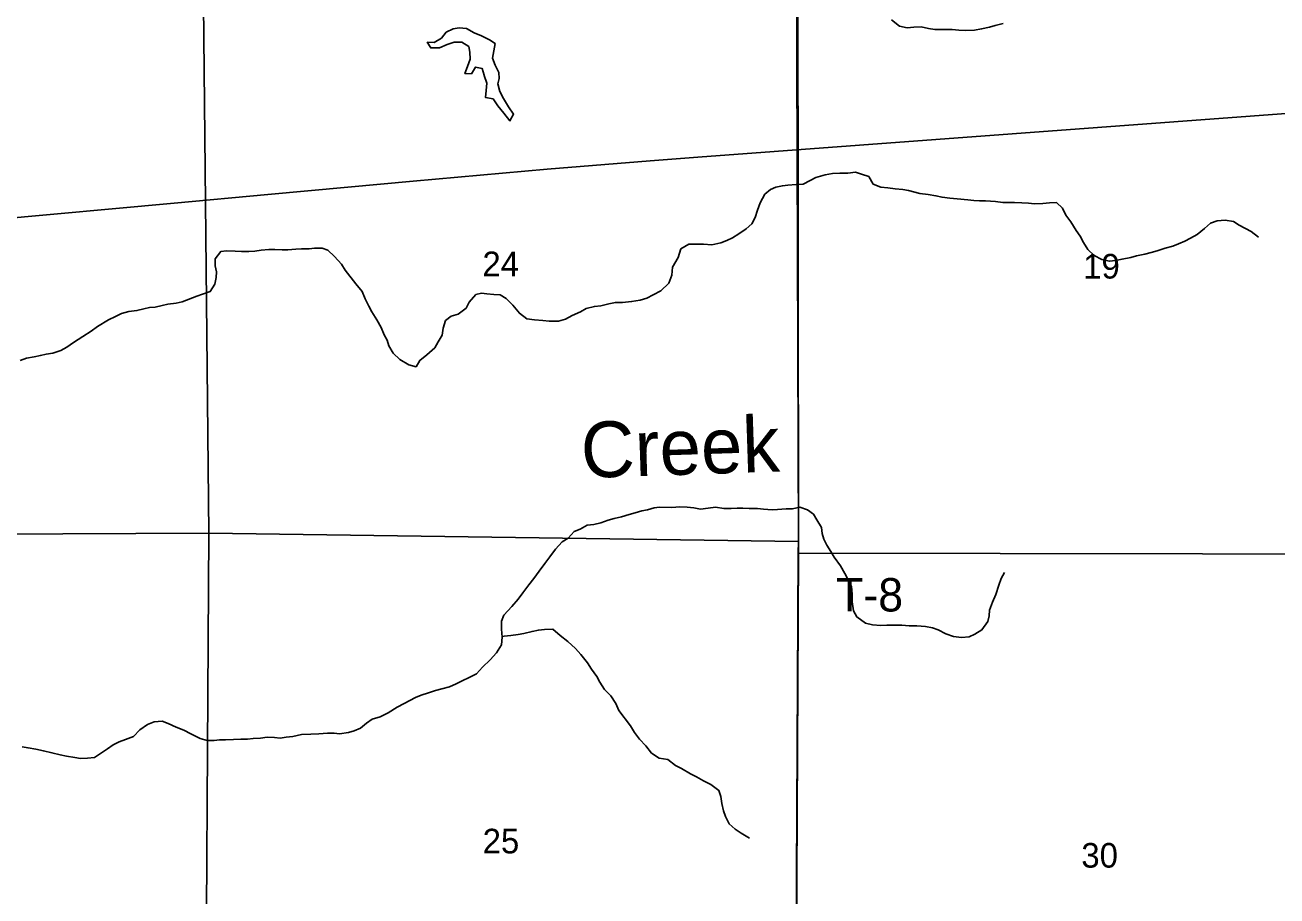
# Model space of a CAD drawing. Extents: x 1772825 to 1773716, y 1138558 to 1139032.
# Drawn here: x 1772830.361 to 1772831.426, y 1138561.834 to 1138562.575 of the extents above; entities that cross this region are included whole.
import ezdxf

# ---------------------------------------------------------------- set-up
doc = ezdxf.new("R2010")
doc.units = 0
for name, color, linetype in [('GM_X_Minor_Lake', 7, 'Continuous'), ('GM_X_Minor_River', 7, 'Continuous'), ('GM_X_Minor_River_Text', 7, 'Continuous'), ('GM_X_Rail_Line', 7, 'Continuous'), ('GM_X_Section', 7, 'Continuous'), ('GM_X_Section_Text', 7, 'Continuous'), ('GM_X_Township', 7, 'Continuous'), ('GM_X_Township_Road_Text', 7, 'Continuous')]:
    doc.layers.add(name, color=color, linetype=linetype)

msp = doc.modelspace()

# ---------------------------------------------------------------- linework, layer by layer
at = {"layer": 'GM_X_Minor_Lake'}
for points in [[(1772830.7608, 1138562.5591), (1772830.7559, 1138562.5621), (1772830.7493, 1138562.5656), (1772830.743, 1138562.5682), (1772830.7364, 1138562.5717), (1772830.7301, 1138562.5723), (1772830.7252, 1138562.5714), (1772830.7193, 1138562.5687), (1772830.7153, 1138562.5636), (1772830.709, 1138562.56), (1772830.7031, 1138562.5601), (1772830.7061, 1138562.5553), (1772830.7135, 1138562.5555), (1772830.72, 1138562.5583), (1772830.7261, 1138562.5603), (1772830.7325, 1138562.5603), (1772830.7384, 1138562.5565), (1772830.7393, 1138562.5518), (1772830.7397, 1138562.5457), (1772830.7372, 1138562.5396), (1772830.7351, 1138562.5335), (1772830.7406, 1138562.5333), (1772830.744, 1138562.539), (1772830.7497, 1138562.5379), (1772830.7515, 1138562.5322)], [(1772830.7515, 1138562.5322), (1772830.7516, 1138562.5318), (1772830.7538, 1138562.5253), (1772830.7531, 1138562.5192), (1772830.7526, 1138562.5132), (1772830.7591, 1138562.512), (1772830.7631, 1138562.5061), (1772830.7683, 1138562.4998), (1772830.7734, 1138562.4933), (1772830.7765, 1138562.499), (1772830.7722, 1138562.5053), (1772830.768, 1138562.5122), (1772830.7648, 1138562.5182), (1772830.7631, 1138562.5247), (1772830.7643, 1138562.5294), (1772830.7639, 1138562.5344), (1772830.7609, 1138562.5407), (1772830.7587, 1138562.5467), (1772830.7608, 1138562.5591)]]:
    msp.add_lwpolyline(points, dxfattribs=at)
at = {"layer": 'GM_X_Minor_River'}
for points in [[(1772831.098, 1138562.5791), (1772831.1048, 1138562.5737), (1772831.1114, 1138562.5724), (1772831.1169, 1138562.5729), (1772831.1232, 1138562.5731), (1772831.1295, 1138562.5719), (1772831.1348, 1138562.571), (1772831.1496, 1138562.5709), (1772831.1551, 1138562.5703), (1772831.1613, 1138562.5701), (1772831.1684, 1138562.5704), (1772831.1746, 1138562.5714), (1772831.1813, 1138562.5729), (1772831.1862, 1138562.5743), (1772831.1929, 1138562.5762)], [(1772830.7879, 1138562.3249), (1772830.7944, 1138562.3242), (1772830.8014, 1138562.3234), (1772830.8069, 1138562.323), (1772830.8147, 1138562.3229), (1772830.8208, 1138562.3248), (1772830.8263, 1138562.3278), (1772830.8335, 1138562.331), (1772830.8383, 1138562.3338), (1772830.8453, 1138562.3355), (1772830.8506, 1138562.3359), (1772830.8574, 1138562.3377), (1772830.8631, 1138562.3389), (1772830.8692, 1138562.3388), (1772830.8768, 1138562.3396), (1772830.8842, 1138562.3409), (1772830.8897, 1138562.3424), (1772830.8951, 1138562.3454), (1772830.9017, 1138562.3488), (1772830.9086, 1138562.3554), (1772830.9111, 1138562.362), (1772830.9117, 1138562.3688), (1772830.9164, 1138562.3772), (1772830.9189, 1138562.3844), (1772830.9256, 1138562.3883), (1772830.9321, 1138562.3885), (1772830.9381, 1138562.3883), (1772830.9451, 1138562.3879), (1772830.9529, 1138562.3897), (1772830.9579, 1138562.3916), (1772830.9626, 1138562.3939), (1772830.9682, 1138562.3971), (1772830.9744, 1138562.4016), (1772830.9792, 1138562.4057), (1772830.9821, 1138562.411), (1772830.984, 1138562.4173), (1772830.9863, 1138562.4237), (1772830.9901, 1138562.4309), (1772830.9949, 1138562.4349), (1772830.9996, 1138562.437), (1772831.0051, 1138562.4381), (1772831.0099, 1138562.4386), (1772831.0169, 1138562.4392), (1772831.0228, 1138562.4395), (1772831.0287, 1138562.4427), (1772831.0336, 1138562.4452), (1772831.0414, 1138562.4474), (1772831.0479, 1138562.4485), (1772831.054, 1138562.4487), (1772831.0608, 1138562.4489), (1772831.0674, 1138562.4496), (1772831.0724, 1138562.4479), (1772831.0786, 1138562.4461), (1772831.0824, 1138562.4395), (1772831.089, 1138562.437), (1772831.0947, 1138562.4362), (1772831.1012, 1138562.4354), (1772831.1076, 1138562.4348), (1772831.1124, 1138562.434), (1772831.122, 1138562.4315), (1772831.1291, 1138562.4307), (1772831.1357, 1138562.4296), (1772831.141, 1138562.4284), (1772831.1476, 1138562.4276), (1772831.1539, 1138562.427), (1772831.1628, 1138562.4262), (1772831.1679, 1138562.4256), (1772831.1729, 1138562.4252), (1772831.178, 1138562.4252), (1772831.1863, 1138562.4246), (1772831.1926, 1138562.424), (1772831.1974, 1138562.424), (1772831.2027, 1138562.4238), (1772831.2087, 1138562.4236), (1772831.2146, 1138562.4232), (1772831.2196, 1138562.4228), (1772831.2266, 1138562.4229), (1772831.2323, 1138562.4235), (1772831.2384, 1138562.4238), (1772831.2433, 1138562.4191), (1772831.2463, 1138562.413), (1772831.2504, 1138562.4074), (1772831.2551, 1138562.4), (1772831.2585, 1138562.3951), (1772831.2612, 1138562.3899), (1772831.2648, 1138562.384), (1772831.2704, 1138562.3789), (1772831.2769, 1138562.3755), (1772831.2833, 1138562.3739), (1772831.2886, 1138562.3745), (1772831.2941, 1138562.3758), (1772831.3014, 1138562.3772), (1772831.3063, 1138562.3784), (1772831.3133, 1138562.38), (1772831.3188, 1138562.3813), (1772831.3238, 1138562.3828), (1772831.3308, 1138562.3849), (1772831.3373, 1138562.3868), (1772831.342, 1138562.3887), (1772831.3473, 1138562.3909), (1772831.3523, 1138562.3934)], [(1772831.3523, 1138562.3934), (1772831.3578, 1138562.3966), (1772831.3643, 1138562.4018), (1772831.3692, 1138562.4062), (1772831.3749, 1138562.4083), (1772831.3818, 1138562.4088), (1772831.3888, 1138562.4076), (1772831.3937, 1138562.4046), (1772831.4039, 1138562.3992), (1772831.4102, 1138562.3944)], [(1772830.3569, 1138562.2894), (1772830.3623, 1138562.2914), (1772830.3687, 1138562.2927), (1772830.374, 1138562.2939), (1772830.379, 1138562.295), (1772830.3845, 1138562.2957), (1772830.3913, 1138562.298), (1772830.3965, 1138562.3008), (1772830.4022, 1138562.3047), (1772830.4102, 1138562.3098), (1772830.4172, 1138562.3144), (1772830.4225, 1138562.3183), (1772830.432, 1138562.324), (1772830.4378, 1138562.327), (1772830.4431, 1138562.3296), (1772830.4494, 1138562.3311), (1772830.4562, 1138562.332), (1772830.4621, 1138562.3335), (1772830.4668, 1138562.3345), (1772830.4716, 1138562.3348), (1772830.4777, 1138562.3363), (1772830.4824, 1138562.3374), (1772830.4894, 1138562.3383), (1772830.4946, 1138562.3395), (1772830.5071, 1138562.3443), (1772830.512, 1138562.3458), (1772830.5185, 1138562.3483), (1772830.5223, 1138562.3543), (1772830.5235, 1138562.3602), (1772830.5237, 1138562.365), (1772830.5228, 1138562.3699), (1772830.5228, 1138562.376), (1772830.5274, 1138562.3822), (1772830.5323, 1138562.3828), (1772830.5397, 1138562.3824), (1772830.545, 1138562.3821), (1772830.5513, 1138562.3821), (1772830.5564, 1138562.3825), (1772830.5617, 1138562.3832), (1772830.5684, 1138562.3839), (1772830.5733, 1138562.3839), (1772830.5798, 1138562.3837), (1772830.5845, 1138562.3837), (1772830.5912, 1138562.3842), (1772830.5961, 1138562.3844), (1772830.6026, 1138562.3846), (1772830.6073, 1138562.3851), (1772830.6138, 1138562.3849), (1772830.6185, 1138562.3832), (1772830.6243, 1138562.378), (1772830.6302, 1138562.3713), (1772830.6332, 1138562.3662), (1772830.6423, 1138562.3548), (1772830.6478, 1138562.3483), (1772830.6504, 1138562.342), (1772830.6534, 1138562.3358), (1772830.656, 1138562.3308), (1772830.6602, 1138562.324), (1772830.6638, 1138562.3177), (1772830.6664, 1138562.3114), (1772830.669, 1138562.3067), (1772830.6705, 1138562.3019), (1772830.6741, 1138562.2958), (1772830.6798, 1138562.2903), (1772830.6874, 1138562.2857), (1772830.6936, 1138562.2842), (1772830.6967, 1138562.2896), (1772830.7026, 1138562.2944), (1772830.7096, 1138562.3004), (1772830.7123, 1138562.3055), (1772830.7159, 1138562.311), (1772830.7167, 1138562.3171), (1772830.7186, 1138562.3235), (1772830.7234, 1138562.3271), (1772830.7295, 1138562.329), (1772830.7361, 1138562.3339), (1772830.7388, 1138562.3392), (1772830.7444, 1138562.3456), (1772830.7491, 1138562.3467), (1772830.7538, 1138562.3462), (1772830.7597, 1138562.3457), (1772830.7652, 1138562.3453), (1772830.7702, 1138562.3421), (1772830.776, 1138562.3366), (1772830.7815, 1138562.3297), (1772830.7879, 1138562.3249)], [(1772830.7329, 1138562.017), (1772830.7388, 1138562.02), (1772830.7451, 1138562.023), (1772830.75, 1138562.0288), (1772830.7567, 1138562.0349), (1772830.7619, 1138562.0409), (1772830.7661, 1138562.0478), (1772830.7669, 1138562.0542), (1772830.7663, 1138562.061), (1772830.7663, 1138562.0679), (1772830.7681, 1138562.073), (1772830.7751, 1138562.0804), (1772830.7803, 1138562.0866), (1772830.7845, 1138562.0921), (1772830.7894, 1138562.0989), (1772830.7938, 1138562.1042), (1772830.7982, 1138562.1104), (1772830.803, 1138562.1169), (1772830.8074, 1138562.1225), (1772830.8122, 1138562.1292), (1772830.8179, 1138562.1352), (1772830.823, 1138562.1384), (1772830.828, 1138562.1441), (1772830.8331, 1138562.1462), (1772830.8392, 1138562.1494), (1772830.8447, 1138562.1501), (1772830.8508, 1138562.1514), (1772830.857, 1138562.1538), (1772830.862, 1138562.1553), (1772830.8683, 1138562.1565), (1772830.8747, 1138562.1587), (1772830.88, 1138562.16), (1772830.8856, 1138562.1617), (1772830.8903, 1138562.1626), (1772830.896, 1138562.1641), (1772830.9007, 1138562.1647), (1772830.911, 1138562.1646), (1772830.9178, 1138562.1652), (1772830.9241, 1138562.1649), (1772830.9298, 1138562.1642), (1772830.9355, 1138562.1632), (1772830.9419, 1138562.1639), (1772830.9482, 1138562.1648), (1772830.9554, 1138562.1637), (1772830.9615, 1138562.1638), (1772830.9666, 1138562.164), (1772830.9715, 1138562.164), (1772830.9769, 1138562.1636), (1772830.9839, 1138562.1637), (1772830.9892, 1138562.1632), (1772830.9964, 1138562.1626), (1772831.0011, 1138562.1627), (1772831.0084, 1138562.1635), (1772831.0137, 1138562.1634), (1772831.0199, 1138562.1647), (1772831.0266, 1138562.1626), (1772831.0315, 1138562.1588), (1772831.0345, 1138562.1539), (1772831.0383, 1138562.1474), (1772831.039, 1138562.1424), (1772831.0405, 1138562.1375), (1772831.043, 1138562.1326), (1772831.0464, 1138562.1272), (1772831.0492, 1138562.1223), (1772831.0545, 1138562.1149), (1772831.0582, 1138562.1084), (1772831.0607, 1138562.1036), (1772831.0639, 1138562.0974), (1772831.0644, 1138562.0907), (1772831.0646, 1138562.0843), (1772831.0657, 1138562.0767), (1772831.0685, 1138562.0715), (1772831.0757, 1138562.0662), (1772831.0818, 1138562.0648), (1772831.0888, 1138562.0642), (1772831.0939, 1138562.0646), (1772831.0998, 1138562.0644), (1772831.1066, 1138562.0644), (1772831.1129, 1138562.0639), (1772831.1194, 1138562.0639), (1772831.1268, 1138562.0633), (1772831.1328, 1138562.0623), (1772831.1377, 1138562.0604), (1772831.1442, 1138562.0572), (1772831.1506, 1138562.0549), (1772831.1575, 1138562.0541), (1772831.1639, 1138562.0546), (1772831.1689, 1138562.0569), (1772831.1749, 1138562.0605), (1772831.1799, 1138562.0676), (1772831.1809, 1138562.0724), (1772831.1813, 1138562.0771), (1772831.1838, 1138562.084), (1772831.1867, 1138562.0906), (1772831.1892, 1138562.0984), (1772831.1911, 1138562.1042), (1772831.1941, 1138562.1092)], [(1772830.7668, 1138562.0548), (1772830.7684, 1138562.055), (1772830.7743, 1138562.0557), (1772830.7803, 1138562.0566), (1772830.7853, 1138562.0575), (1772830.7923, 1138562.0592), (1772830.7976, 1138562.0603), (1772830.8029, 1138562.0609), (1772830.8098, 1138562.061), (1772830.8162, 1138562.0557), (1772830.8226, 1138562.0507), (1772830.8291, 1138562.0446), (1772830.8336, 1138562.0395), (1772830.8393, 1138562.0325), (1772830.8429, 1138562.0271), (1772830.8472, 1138562.0208), (1772830.85, 1138562.0161), (1772830.8538, 1138562.0098), (1772830.8591, 1138562.0045), (1772830.8636, 1138561.9978), (1772830.866, 1138561.9919), (1772830.8759, 1138561.979), (1772830.8793, 1138561.9731), (1772830.8836, 1138561.9676), (1772830.8889, 1138561.962), (1772830.8938, 1138561.9557), (1772830.9002, 1138561.9513), (1772830.9076, 1138561.9502), (1772830.9141, 1138561.9452), (1772830.9194, 1138561.9427), (1772830.9269, 1138561.938), (1772830.9321, 1138561.9355), (1772830.9381, 1138561.9322), (1772830.9444, 1138561.929), (1772830.951, 1138561.924), (1772830.9527, 1138561.9189), (1772830.9536, 1138561.9128), (1772830.9551, 1138561.9067), (1772830.9568, 1138561.9018), (1772830.9598, 1138561.8955), (1772830.9649, 1138561.8909), (1772830.97, 1138561.8877), (1772830.9772, 1138561.8833)], [(1772830.3586, 1138561.961), (1772830.3635, 1138561.9601), (1772830.3702, 1138561.9589), (1772830.3766, 1138561.9575), (1772830.3838, 1138561.956), (1772830.3908, 1138561.9543), (1772830.3963, 1138561.9531), (1772830.4034, 1138561.9519), (1772830.4081, 1138561.9511), (1772830.414, 1138561.9515), (1772830.4201, 1138561.952), (1772830.4252, 1138561.9553), (1772830.4311, 1138561.9594), (1772830.4358, 1138561.9626), (1772830.441, 1138561.9652), (1772830.4465, 1138561.9673), (1772830.4532, 1138561.9699), (1772830.4587, 1138561.9754), (1772830.4652, 1138561.9799), (1772830.4707, 1138561.9824), (1772830.4777, 1138561.9827), (1772830.4826, 1138561.9808), (1772830.4896, 1138561.9778), (1772830.4959, 1138561.9753), (1772830.5021, 1138561.9722), (1772830.5099, 1138561.9682), (1772830.5158, 1138561.9664), (1772830.5217, 1138561.9664), (1772830.5264, 1138561.967), (1772830.5315, 1138561.9669), (1772830.5384, 1138561.9673), (1772830.5444, 1138561.9675), (1772830.5501, 1138561.9674), (1772830.5551, 1138561.968), (1772830.5613, 1138561.9683), (1772830.567, 1138561.9691), (1772830.5731, 1138561.9689), (1772830.578, 1138561.9685), (1772830.583, 1138561.9692), (1772830.5887, 1138561.9699), (1772830.5961, 1138561.9714), (1772830.604, 1138561.9718), (1772830.6109, 1138561.9721), (1772830.6181, 1138561.9725), (1772830.6238, 1138561.9726), (1772830.6285, 1138561.9722), (1772830.6361, 1138561.9732), (1772830.6409, 1138561.9745), (1772830.6464, 1138561.9769), (1772830.6513, 1138561.9811), (1772830.6561, 1138561.9846), (1772830.6631, 1138561.9865), (1772830.6698, 1138561.9899), (1772830.6774, 1138561.9948), (1772830.6835, 1138561.998), (1772830.6882, 1138562.0003), (1772830.693, 1138562.0029), (1772830.6978, 1138562.005), (1772830.7042, 1138562.0068), (1772830.7101, 1138562.0089), (1772830.7156, 1138562.0104), (1772830.7219, 1138562.0121), (1772830.7276, 1138562.0147), (1772830.7329, 1138562.017)]]:
    msp.add_lwpolyline(points, dxfattribs=at)
at = {"layer": 'GM_X_Rail_Line'}
msp.add_lwpolyline([(1772830.3325, 1138562.4092), (1772830.4879, 1138562.4234), (1772830.5676, 1138562.4306), (1772830.6355, 1138562.4369), (1772830.6911, 1138562.442), (1772830.8052, 1138562.4523), (1772830.8926, 1138562.4594), (1772830.9332, 1138562.4624), (1772831.5406, 1138562.5076)], dxfattribs=at)
at = {"layer": 'GM_X_Section'}
for points in [[(1772830.5121, 1138562.649), (1772830.5173, 1138562.1427), (1772830.0206, 1138562.1405), (1772830.0203, 1138562.6461)], [(1772830.5121, 1138562.649), (1772831.0168, 1138562.6374), (1772831.0172, 1138562.6264), (1772831.0189, 1138562.1356), (1772830.5173, 1138562.1427)], [(1772831.0172, 1138562.6264), (1772831.5404, 1138562.6267), (1772831.5343, 1138562.1249), (1772831.0185, 1138562.1256), (1772831.0189, 1138562.1356)], [(1772830.0206, 1138562.1405), (1772830.5173, 1138562.1427), (1772830.5141, 1138561.637), (1772830.0151, 1138561.6359)], [(1772830.5173, 1138562.1427), (1772831.0189, 1138562.1356), (1772831.0185, 1138562.1256), (1772831.016, 1138561.6326), (1772830.5141, 1138561.637)], [(1772831.0185, 1138562.1256), (1772831.5343, 1138562.1249), (1772831.5342, 1138561.6281), (1772831.016, 1138561.6229), (1772831.016, 1138561.6326)]]:
    msp.add_lwpolyline(points, close=True, dxfattribs=at)
at = {"layer": 'GM_X_Township'}
for points in [[(1772829.0062, 1138564.1402), (1772829.258, 1138564.138), (1772829.3013, 1138564.1384), (1772829.5426, 1138564.1379), (1772829.6188, 1138564.1396), (1772829.7041, 1138564.1368), (1772829.7207, 1138564.137), (1772829.8486, 1138564.1368), (1772830.2648, 1138564.1416), (1772830.3453, 1138564.145), (1772830.4944, 1138564.15), (1772831.0202, 1138564.1762), (1772831.0121, 1138563.891), (1772831.0052, 1138563.6394), (1772831.0051, 1138563.6356), (1772831.0123, 1138563.1356), (1772831.0184, 1138562.6335), (1772831.0189, 1138562.1254), (1772831.0162, 1138561.6278)], [(1772832.1579, 1138564.1796), (1772832.0716, 1138564.1801), (1772832.0538, 1138564.1803), (1772831.5706, 1138564.1819), (1772831.5563, 1138564.1819), (1772831.0202, 1138564.1762), (1772831.0121, 1138563.891), (1772831.0052, 1138563.6394), (1772831.0051, 1138563.6356), (1772831.0123, 1138563.1356), (1772831.0184, 1138562.6335), (1772831.0189, 1138562.1254), (1772831.0162, 1138561.6278), (1772831.0118, 1138561.1299), (1772831.4841, 1138561.1316), (1772831.5117, 1138561.1318), (1772832.1579, 1138561.1331)]]:
    msp.add_lwpolyline(points, dxfattribs=at)

# ---------------------------------------------------------------- texts
at = {"layer": 'GM_X_Minor_River_Text'}
msp.add_text('Creek', height=0.04737, rotation=1.8816, dxfattribs=at).set_placement((1772830.8345, 1138562.1896))
at = {"layer": 'GM_X_Section_Text'}
for s, p in [('24', (1772830.75, 1138562.3612)), ('19', (1772831.261, 1138562.3592)), ('25', (1772830.7502, 1138561.8704)), ('30', (1772831.2594, 1138561.8583))]:
    msp.add_text(s, height=0.02093, rotation=0, dxfattribs=at).set_placement(p)
at = {"layer": 'GM_X_Township_Road_Text'}
msp.add_text('T-8', height=0.02841, rotation=0, dxfattribs=at).set_placement((1772831.0508, 1138562.0761))

doc.saveas('drawing.dxf')
